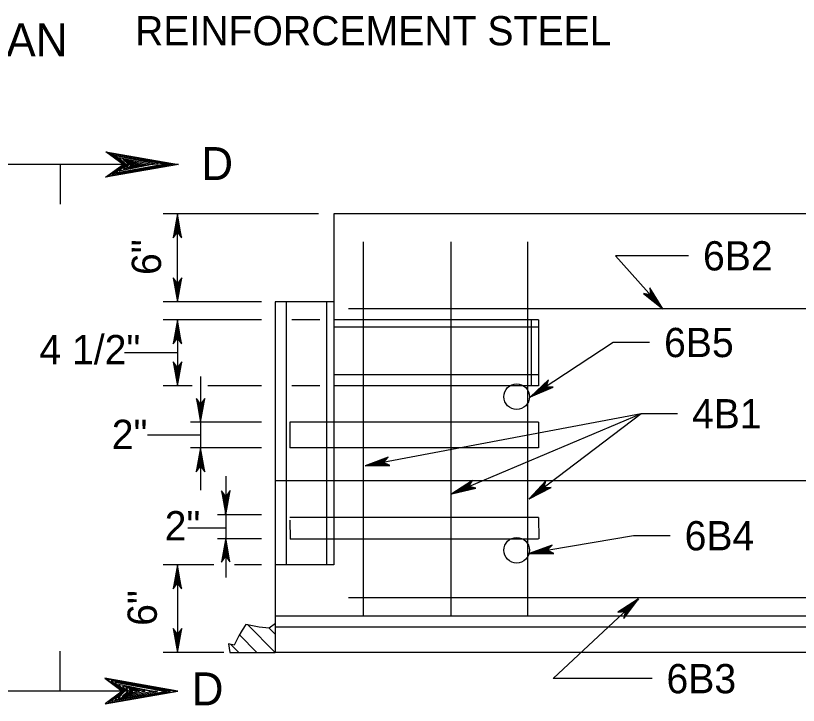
# Model space of a CAD drawing. Extents: x 499883 to 500983, y 499104 to 499764.
# Drawn here: x 500121.3 to 500228.2, y 499574 to 499668.3 of the extents above; entities that cross this region are included whole.
import ezdxf

# ---------------------------------------------------------------- set-up
doc = ezdxf.new("R2010")
doc.units = 0
for name, color, linetype in [('2', 7, 'Continuous'), ('24', 7, 'Continuous'), ('5', 7, 'Continuous'), ('60', 7, 'Continuous')]:
    doc.layers.add(name, color=color, linetype=linetype)

msp = doc.modelspace()

# ---------------------------------------------------------------- linework, layer by layer
at = {"layer": '2'}
for p, q in [((500127.4, 499642.49), (500127.4, 499647.93)), ((500127.3, 499581.39), (500127.3, 499575.94))]:
    msp.add_line(p, q, dxfattribs=at)
at = {"layer": '24'}
for points in [[(500143.38, 499641.16), (500142.8, 499637.88), (500143.38, 499638.66), (500143.95, 499637.9), (500143.38, 499641.16), (500143.39, 499640.94), (500142.85, 499637.97), (500143.39, 499638.73), (500143.91, 499638.03), (500143.4, 499640.82), (500143.38, 499640.71), (500142.93, 499638.17), (500143.39, 499638.74), (500143.83, 499638.16), (500143.38, 499640.66), (500143.4, 499640.55), (500143, 499638.33), (500143.38, 499638.77), (500143.78, 499638.32), (500143.4, 499640.24), (500143.4, 499640.05), (500143.08, 499638.5), (500143.37, 499638.8), (500143.7, 499638.48), (500143.38, 499640.02), (500143.37, 499639.85), (500143.17, 499638.68), (500143.4, 499638.9), (500143.62, 499638.66), (500143.38, 499639.68), (500143.37, 499639.52), (500143.23, 499638.82), (500143.39, 499638.93), (500143.56, 499638.74), (500143.38, 499639.43), (500143.27, 499638.98), (500143.4, 499639.04), (500143.52, 499638.84), (500143.4, 499639.32), (500143.32, 499639.02), (500143.42, 499639.14), (500143.48, 499639), (500143.39, 499639.14), (500143.37, 499639.07)], [(500143.38, 499629.17), (500143.96, 499632.44), (500143.38, 499631.66), (500142.81, 499632.42), (500143.38, 499629.17), (500143.38, 499629.38), (500143.92, 499632.35), (500143.38, 499631.6), (500142.86, 499632.29), (500143.37, 499629.5), (500143.38, 499629.61), (500143.83, 499632.15), (500143.38, 499631.58), (500142.93, 499632.17), (500143.38, 499629.66), (500143.37, 499629.77), (500143.77, 499631.99), (500143.38, 499631.56), (500142.98, 499632), (500143.37, 499630.08), (500143.37, 499630.27), (500143.68, 499631.82), (500143.39, 499631.52), (500143.07, 499631.85), (500143.38, 499630.3), (500143.39, 499630.48), (500143.59, 499631.65), (500143.37, 499631.42), (500143.14, 499631.66), (500143.38, 499630.64), (500143.4, 499630.8), (500143.53, 499631.5), (500143.38, 499631.39), (500143.2, 499631.58), (500143.38, 499630.89), (500143.49, 499631.35), (500143.37, 499631.28), (500143.24, 499631.48), (500143.37, 499631), (500143.44, 499631.3), (500143.34, 499631.18), (500143.28, 499631.32), (500143.38, 499631.18), (500143.39, 499631.25)], [(500143.38, 499626.67), (500142.8, 499623.39), (500143.38, 499624.18), (500143.95, 499623.41), (500143.38, 499626.67), (500143.39, 499626.45), (500142.85, 499623.49), (500143.39, 499624.24), (500143.91, 499623.54), (500143.4, 499626.33), (500143.38, 499626.22), (500142.93, 499623.68), (500143.39, 499624.25), (500143.83, 499623.67), (500143.38, 499626.17), (500143.4, 499626.07), (500143, 499623.84), (500143.38, 499624.28), (500143.78, 499623.84), (500143.4, 499625.75), (500143.4, 499625.56), (500143.08, 499624.01), (500143.37, 499624.31), (500143.7, 499623.99), (500143.38, 499625.53), (500143.37, 499625.36), (500143.17, 499624.19), (500143.4, 499624.41), (500143.62, 499624.17), (500143.38, 499625.2), (500143.37, 499625.03), (500143.23, 499624.33), (500143.39, 499624.44), (500143.56, 499624.25), (500143.38, 499624.95), (500143.27, 499624.49), (500143.4, 499624.55), (500143.52, 499624.35), (500143.4, 499624.83), (500143.32, 499624.53), (500143.42, 499624.66), (500143.48, 499624.51), (500143.39, 499624.66), (500143.37, 499624.58)], [(500143.38, 499617.67), (500143.96, 499620.95), (500143.38, 499620.17), (500142.81, 499620.93), (500143.38, 499617.67), (500143.38, 499617.89), (500143.92, 499620.86), (500143.38, 499620.11), (500142.86, 499620.8), (500143.37, 499618.01), (500143.38, 499618.12), (500143.83, 499620.66), (500143.38, 499620.09), (500142.93, 499620.67), (500143.38, 499618.17), (500143.37, 499618.28), (500143.77, 499620.5), (500143.38, 499620.07), (500142.98, 499620.51), (500143.37, 499618.59), (500143.37, 499618.78), (500143.68, 499620.33), (500143.39, 499620.03), (500143.07, 499620.36), (500143.38, 499618.81), (500143.39, 499618.99), (500143.59, 499620.15), (500143.37, 499619.93), (500143.14, 499620.17), (500143.38, 499619.15), (500143.4, 499619.31), (500143.53, 499620.01), (500143.38, 499619.9), (500143.2, 499620.09), (500143.38, 499619.4), (500143.49, 499619.85), (500143.37, 499619.79), (500143.24, 499619.99), (500143.37, 499619.51), (500143.44, 499619.81), (500143.34, 499619.69), (500143.28, 499619.83), (500143.38, 499619.69), (500143.39, 499619.76)], [(500146.53, 499612.68), (500147.11, 499615.95), (500146.53, 499615.17), (500145.96, 499615.94), (500146.53, 499612.68), (500146.52, 499612.9), (500147.06, 499615.86), (500146.52, 499615.11), (500146, 499615.8), (500146.51, 499613.01), (500146.53, 499613.12), (500146.98, 499615.66), (500146.52, 499615.09), (500146.08, 499615.68), (500146.53, 499613.17), (500146.51, 499613.28), (500146.91, 499615.5), (500146.53, 499615.07), (500146.13, 499615.51), (500146.51, 499613.6), (500146.51, 499613.78), (500146.83, 499615.34), (500146.54, 499615.03), (500146.21, 499615.36), (500146.53, 499613.81), (500146.54, 499613.99), (500146.74, 499615.16), (500146.51, 499614.93), (500146.29, 499615.18), (500146.53, 499614.15), (500146.55, 499614.31), (500146.68, 499615.02), (500146.52, 499614.9), (500146.35, 499615.09), (500146.53, 499614.4), (500146.64, 499614.86), (500146.51, 499614.79), (500146.39, 499614.99), (500146.51, 499614.52), (500146.59, 499614.82), (500146.49, 499614.69), (500146.43, 499614.83), (500146.52, 499614.69), (500146.54, 499614.77)], [(500146.53, 499609.18), (500145.95, 499605.91), (500146.53, 499606.69), (500147.1, 499605.92), (500146.53, 499609.18), (500146.53, 499608.96), (500145.99, 499606), (500146.54, 499606.75), (500147.05, 499606.06), (500146.54, 499608.85), (500146.53, 499608.74), (500146.08, 499606.2), (500146.54, 499606.77), (500146.98, 499606.18), (500146.53, 499608.69), (500146.54, 499608.58), (500146.14, 499606.36), (500146.53, 499606.79), (500146.93, 499606.35), (500146.55, 499608.26), (500146.54, 499608.08), (500146.23, 499606.52), (500146.52, 499606.83), (500146.84, 499606.5), (500146.53, 499608.04), (500146.52, 499607.87), (500146.32, 499606.7), (500146.55, 499606.93), (500146.77, 499606.68), (500146.53, 499607.71), (500146.51, 499607.54), (500146.38, 499606.84), (500146.54, 499606.96), (500146.71, 499606.77), (500146.53, 499607.46), (500146.42, 499607), (500146.54, 499607.07), (500146.67, 499606.87), (500146.55, 499607.34), (500146.47, 499607.04), (500146.57, 499607.17), (500146.63, 499607.02), (500146.54, 499607.17), (500146.52, 499607.09)], [(500143.38, 499593.19), (500142.8, 499589.92), (500143.38, 499590.7), (500143.95, 499589.94), (500143.38, 499593.19), (500143.39, 499592.98), (500142.85, 499590.01), (500143.39, 499590.76), (500143.91, 499590.07), (500143.4, 499592.86), (500143.38, 499592.75), (500142.93, 499590.21), (500143.39, 499590.78), (500143.83, 499590.19), (500143.38, 499592.7), (500143.4, 499592.59), (500143, 499590.37), (500143.38, 499590.8), (500143.78, 499590.36), (500143.4, 499592.27), (500143.4, 499592.09), (500143.08, 499590.54), (500143.37, 499590.84), (500143.7, 499590.51), (500143.38, 499592.06), (500143.37, 499591.88), (500143.17, 499590.71), (500143.4, 499590.94), (500143.62, 499590.69), (500143.38, 499591.72), (500143.37, 499591.56), (500143.23, 499590.85), (500143.39, 499590.97), (500143.56, 499590.78), (500143.38, 499591.47), (500143.27, 499591.01), (500143.4, 499591.08), (500143.52, 499590.88), (500143.4, 499591.36), (500143.32, 499591.06), (500143.42, 499591.18), (500143.48, 499591.04), (500143.39, 499591.18), (500143.37, 499591.11)], [(500206.38, 499588.55), (500203.55, 499586.71), (500204.53, 499586.82), (500204.36, 499585.87), (500206.38, 499588.55), (500206.22, 499588.39), (500203.65, 499586.74), (500204.58, 499586.86), (500204.42, 499585.99), (500206.14, 499588.3), (500206.05, 499588.24), (500203.85, 499586.81), (500204.59, 499586.87), (500204.47, 499586.13), (500206.01, 499588.2), (500205.94, 499588.12), (500204.02, 499586.88), (500204.61, 499586.89), (500204.55, 499586.29), (500205.71, 499587.9), (500205.57, 499587.77), (500204.2, 499586.93), (500204.63, 499586.92), (500204.61, 499586.45), (500205.54, 499587.76), (500205.4, 499587.65), (500204.39, 499586.98), (500204.72, 499586.97), (500204.69, 499586.64), (500205.29, 499587.53), (500205.15, 499587.42), (500204.54, 499587.04), (500204.73, 499587), (500204.71, 499586.74), (500205.1, 499587.35), (500204.69, 499587.12), (500204.82, 499587.07), (500204.76, 499586.84), (500205.03, 499587.26), (500204.75, 499587.11), (500204.91, 499587.12), (500204.85, 499586.98), (500204.89, 499587.15), (500204.82, 499587.11)], [(500143.38, 499581.22), (500143.96, 499584.5), (500143.38, 499583.71), (500142.81, 499584.48), (500143.38, 499581.22), (500143.38, 499581.44), (500143.92, 499584.4), (500143.38, 499583.65), (500142.86, 499584.35), (500143.37, 499581.56), (500143.38, 499581.67), (500143.83, 499584.2), (500143.38, 499583.64), (500142.93, 499584.22), (500143.38, 499581.72), (500143.37, 499581.82), (500143.77, 499584.04), (500143.38, 499583.61), (500142.98, 499584.05), (500143.37, 499582.14), (500143.37, 499582.32), (500143.68, 499583.88), (500143.39, 499583.58), (500143.07, 499583.9), (500143.38, 499582.36), (500143.39, 499582.53), (500143.59, 499583.7), (500143.37, 499583.48), (500143.14, 499583.72), (500143.38, 499582.69), (500143.4, 499582.86), (500143.53, 499583.56), (500143.38, 499583.44), (500143.2, 499583.64), (500143.38, 499582.94), (500143.49, 499583.4), (500143.37, 499583.34), (500143.24, 499583.54), (500143.37, 499583.06), (500143.44, 499583.36), (500143.34, 499583.23), (500143.28, 499583.38), (500143.38, 499583.23), (500143.39, 499583.31)]]:
    msp.add_lwpolyline(points, dxfattribs=at)
at = {"layer": '5'}
for p, q in [((500127.4, 499647.93), (500117.41, 499647.93)), ((500137.4, 499647.93), (500127.4, 499647.93)), ((500162.66, 499641.16), (500141.43, 499641.16)), ((500143.38, 499629.17), (500143.38, 499641.16)), ((500237.96, 499641.16), (500164.74, 499641.16)), ((500164.74, 499641.16), (500164.74, 499629.17)), ((500168.73, 499637.37), (500168.73, 499586.2)), ((500180.72, 499637.37), (500180.72, 499586.2)), ((500191.22, 499637.37), (500191.22, 499586.2)), ((500213.21, 499635.44), (500203.22, 499635.44)), ((500203.22, 499635.44), (500209.69, 499628.21)), ((500154.87, 499629.17), (500141.43, 499629.17)), ((500156.74, 499629.17), (500156.74, 499581.2)), ((500164.74, 499629.17), (500156.74, 499629.17)), ((500158.24, 499629.17), (500158.24, 499593.19)), ((500163.74, 499629.17), (500163.74, 499593.19)), ((500164.74, 499629.17), (500164.74, 499593.19)), ((500237.96, 499628.17), (500166.73, 499628.17)), ((500154.87, 499626.67), (500141.43, 499626.67)), ((500143.38, 499626.67), (500143.38, 499617.67)), ((500162.85, 499626.67), (500159, 499626.67)), ((500192.71, 499626.67), (500164.74, 499626.67)), ((500191.72, 499626.67), (500191.72, 499617.67)), ((500192.71, 499626.67), (500192.71, 499617.67)), ((500192.71, 499625.67), (500164.74, 499625.67)), ((500202.89, 499623.59), (500191.62, 499616.16)), ((500207.89, 499623.59), (500202.89, 499623.59)), ((500143.38, 499622.17), (500136.12, 499622.17)), ((500146.53, 499618.96), (500146.53, 499612.68)), ((500192.71, 499619.17), (500164.74, 499619.17)), ((500145.37, 499617.67), (500141.43, 499617.67)), ((500154.87, 499617.67), (500147.54, 499617.67)), ((500162.85, 499617.67), (500159, 499617.67)), ((500192.71, 499617.67), (500164.74, 499617.67)), ((500206.71, 499613.85), (500169.02, 499606.72)), ((500206.71, 499613.85), (500180.87, 499602.91)), ((500206.71, 499613.85), (500191.42, 499602.2)), ((500211.7, 499613.85), (500206.71, 499613.85)), ((500154.87, 499612.68), (500145.15, 499612.68)), ((500146.53, 499612.68), (500146.53, 499609.18)), ((500192.71, 499612.68), (500158.74, 499612.68)), ((500158.74, 499612.68), (500158.74, 499609.18)), ((500192.71, 499612.68), (500192.71, 499609.18)), ((500146.53, 499610.93), (500139.27, 499610.93)), ((500154.87, 499609.18), (500145.15, 499609.18)), ((500146.53, 499609.18), (500146.53, 499603.41)), ((500192.71, 499609.18), (500158.74, 499609.18)), ((500149.97, 499605.32), (500149.97, 499600.03)), ((500237.96, 499604.68), (500156.74, 499604.68)), ((500154.87, 499600.03), (500148.84, 499600.03)), ((500149.97, 499600.03), (500149.97, 499596.38)), ((500192.71, 499599.69), (500158.74, 499599.69)), ((500158.74, 499599.32), (500158.77, 499596.69)), ((500192.71, 499599.69), (500192.75, 499596.74)), ((500149.97, 499598.2), (500144.8, 499598.2)), ((500205.7, 499597.18), (500191.42, 499594.77)), ((500210.7, 499597.18), (500205.7, 499597.18)), ((500154.87, 499596.74), (500148.84, 499596.74)), ((500149.97, 499596.74), (500149.97, 499591.47)), ((500192.71, 499596.69), (500158.77, 499596.69)), ((500148.36, 499593.19), (500141.43, 499593.19)), ((500143.38, 499593.19), (500143.38, 499581.22)), ((500154.87, 499593.19), (500151.17, 499593.19)), ((500164.74, 499593.19), (500156.74, 499593.19)), ((500237.96, 499588.7), (500166.73, 499588.7)), ((500194.69, 499577.64), (500206.38, 499588.55)), ((500237.96, 499586.2), (500156.74, 499586.2)), ((500156.74, 499586.2), (500156.74, 499586.2)), ((500152.93, 499585.02), (500156.74, 499581.2)), ((500155.9, 499584.54), (500156.74, 499583.7)), ((500237.96, 499584.7), (500156.74, 499584.7)), ((500151.84, 499583.61), (500154.24, 499581.2)), ((500150.61, 499582.34), (500151.75, 499581.2)), ((500149.69, 499581.21), (500141.43, 499581.21)), ((500237.96, 499581.2), (500156.74, 499581.2)), ((500208.22, 499577.64), (500194.69, 499577.64)), ((500127.3, 499575.94), (500117.31, 499575.94)), ((500137.3, 499575.94), (500127.3, 499575.94))]:
    msp.add_line(p, q, dxfattribs=at)
for points in [[(500143.53, 499647.93), (500133.56, 499646.17), (500135.94, 499647.93), (500133.61, 499649.67), (500143.53, 499647.93), (500142.87, 499647.95), (500133.84, 499646.3), (500136.13, 499647.95), (500134.01, 499649.53), (500142.51, 499647.98), (500142.18, 499647.93), (500134.44, 499646.56), (500136.18, 499647.95), (500134.39, 499649.31), (500142.03, 499647.93), (500141.69, 499647.98), (500134.93, 499646.76), (500136.25, 499647.93), (500134.91, 499649.15), (500140.73, 499647.98), (500140.17, 499647.98), (500135.43, 499647.01), (500136.36, 499647.91), (500135.36, 499648.9), (500140.07, 499647.93), (500139.54, 499647.9), (500135.98, 499647.29), (500136.66, 499647.98), (500135.92, 499648.67), (500139.05, 499647.93), (500138.54, 499647.88), (500136.41, 499647.47), (500136.76, 499647.95), (500136.18, 499648.49), (500138.28, 499647.93), (500136.89, 499647.6), (500137.09, 499647.98), (500136.48, 499648.36), (500137.93, 499647.98), (500137.02, 499647.75), (500137.4, 499648.06), (500136.96, 499648.24), (500137.4, 499647.95), (500137.17, 499647.91)], [(500209.69, 499628.21), (500207.91, 499631.08), (500208.01, 499630.1), (500207.06, 499630.29), (500209.69, 499628.21), (500209.54, 499628.37), (500207.94, 499630.98), (500208.04, 499630.05), (500207.18, 499630.22), (500209.46, 499628.46), (500209.39, 499628.55), (500208.01, 499630.78), (500208.05, 499630.03), (500207.32, 499630.18), (500209.36, 499628.59), (500209.27, 499628.66), (500208.07, 499630.61), (500208.07, 499630.02), (500207.47, 499630.08), (500209.06, 499628.9), (500208.93, 499629.04), (500208.12, 499630.43), (500208.11, 499630), (500207.64, 499630.03), (500208.92, 499629.07), (500208.81, 499629.21), (500208.17, 499630.23), (500208.15, 499629.91), (500207.82, 499629.94), (500208.7, 499629.33), (500208.6, 499629.46), (500208.22, 499630.08), (500208.18, 499629.89), (500207.92, 499629.92), (500208.53, 499629.52), (500208.3, 499629.94), (500208.25, 499629.8), (500208.02, 499629.87), (500208.44, 499629.59), (500208.29, 499629.87), (500208.3, 499629.71), (500208.16, 499629.78), (500208.33, 499629.73), (500208.29, 499629.8)], [(500191.62, 499616.16), (500194.72, 499617.5), (500193.73, 499617.55), (500194.06, 499618.47), (500191.62, 499616.16), (500191.8, 499616.29), (500194.61, 499617.49), (500193.67, 499617.53), (500193.97, 499618.35), (500191.89, 499616.36), (500191.99, 499616.41), (500194.4, 499617.45), (500193.66, 499617.52), (500193.91, 499618.22), (500192.04, 499616.44), (500192.12, 499616.51), (500194.23, 499617.41), (500193.64, 499617.5), (500193.79, 499618.08), (500192.39, 499616.69), (500192.54, 499616.79), (500194.04, 499617.39), (500193.62, 499617.47), (500193.71, 499617.93), (500192.58, 499616.8), (500192.73, 499616.89), (500193.84, 499617.37), (500193.52, 499617.44), (500193.6, 499617.76), (500192.87, 499616.98), (500193.01, 499617.06), (500193.68, 499617.34), (500193.5, 499617.41), (500193.56, 499617.67), (500193.08, 499617.12), (500193.53, 499617.29), (500193.4, 499617.36), (500193.5, 499617.58), (500193.17, 499617.2), (500193.46, 499617.31), (500193.3, 499617.32), (500193.39, 499617.45), (500193.32, 499617.29), (500193.39, 499617.32)], [(500169.02, 499606.72), (500172.4, 499606.76), (500171.51, 499607.19), (500172.16, 499607.91), (500169.02, 499606.72), (500169.24, 499606.77), (500172.3, 499606.79), (500171.45, 499607.19), (500172.04, 499607.84), (500169.35, 499606.8), (500169.46, 499606.81), (500172.08, 499606.84), (500171.43, 499607.18), (500171.93, 499607.74), (500169.51, 499606.82), (500169.62, 499606.85), (500171.91, 499606.87), (500171.41, 499607.17), (500171.77, 499607.66), (500169.94, 499606.91), (500170.12, 499606.95), (500171.73, 499606.92), (500171.37, 499607.16), (500171.64, 499607.54), (500170.16, 499606.94), (500170.33, 499606.96), (500171.54, 499606.98), (500171.27, 499607.16), (500171.47, 499607.43), (500170.49, 499607), (500170.66, 499607.02), (500171.38, 499607.01), (500171.24, 499607.15), (500171.4, 499607.36), (500170.74, 499607.05), (500171.22, 499607.03), (500171.13, 499607.14), (500171.3, 499607.3), (500170.85, 499607.09), (500171.17, 499607.07), (500171.02, 499607.14), (500171.15, 499607.23), (500171.03, 499607.11), (500171.11, 499607.11)], [(500180.87, 499602.91), (500184.16, 499603.66), (500183.2, 499603.89), (500183.69, 499604.73), (500180.87, 499602.91), (500181.07, 499603), (500184.06, 499603.67), (500183.14, 499603.88), (500183.59, 499604.63), (500181.18, 499603.05), (500181.29, 499603.08), (500183.84, 499603.67), (500183.13, 499603.87), (500183.5, 499604.52), (500181.33, 499603.1), (500181.43, 499603.16), (500183.66, 499603.67), (500183.11, 499603.85), (500183.36, 499604.4), (500181.72, 499603.29), (500181.9, 499603.36), (500183.48, 499603.68), (500183.08, 499603.83), (500183.25, 499604.26), (500181.93, 499603.36), (500182.1, 499603.42), (500183.27, 499603.69), (500182.97, 499603.82), (500183.11, 499604.12), (500182.25, 499603.49), (500182.41, 499603.54), (500183.12, 499603.69), (500182.95, 499603.79), (500183.06, 499604.03), (500182.48, 499603.59), (500182.95, 499603.67), (500182.84, 499603.76), (500182.98, 499603.96), (500182.58, 499603.65), (500182.89, 499603.7), (500182.74, 499603.74), (500182.85, 499603.85), (500182.75, 499603.71), (500182.83, 499603.72)], [(500191.42, 499602.2), (500194.42, 499603.75), (500193.43, 499603.74), (500193.7, 499604.67), (500191.42, 499602.2), (500191.59, 499602.34), (500194.32, 499603.73), (500193.38, 499603.7), (500193.62, 499604.55), (500191.68, 499602.42), (500191.78, 499602.48), (500194.1, 499603.67), (500193.36, 499603.69), (500193.56, 499604.41), (500191.82, 499602.51), (500191.89, 499602.59), (500193.93, 499603.63), (500193.35, 499603.67), (500193.46, 499604.27), (500192.15, 499602.78), (500192.3, 499602.9), (500193.75, 499603.59), (500193.32, 499603.65), (500193.39, 499604.11), (500192.33, 499602.9), (500192.48, 499603), (500193.55, 499603.56), (500193.23, 499603.6), (500193.29, 499603.94), (500192.61, 499603.11), (500192.75, 499603.2), (500193.4, 499603.52), (500193.21, 499603.58), (500193.25, 499603.84), (500192.81, 499603.26), (500193.24, 499603.46), (500193.11, 499603.52), (500193.2, 499603.74), (500192.89, 499603.35), (500193.18, 499603.47), (500193.02, 499603.47), (500193.1, 499603.61), (500193.04, 499603.45), (500193.11, 499603.48)], [(500149.97, 499600.03), (500150.56, 499603.35), (500149.97, 499602.56), (500149.39, 499603.33), (500149.97, 499600.03), (500149.96, 499600.25), (500150.51, 499603.26), (500149.96, 499602.49), (500149.44, 499603.2), (500149.95, 499600.37), (500149.97, 499600.48), (500150.43, 499603.05), (500149.96, 499602.48), (500149.51, 499603.07), (500149.97, 499600.53), (500149.95, 499600.64), (500150.36, 499602.89), (500149.97, 499602.45), (500149.56, 499602.9), (500149.95, 499600.96), (500149.95, 499601.15), (500150.27, 499602.72), (500149.98, 499602.42), (500149.65, 499602.75), (500149.97, 499601.18), (500149.98, 499601.36), (500150.18, 499602.54), (500149.95, 499602.32), (500149.72, 499602.56), (500149.97, 499601.52), (500149.98, 499601.69), (500150.12, 499602.4), (500149.96, 499602.28), (500149.78, 499602.48), (500149.97, 499601.77), (500150.08, 499602.24), (500149.95, 499602.17), (500149.82, 499602.38), (500149.95, 499601.89), (500150.03, 499602.2), (500149.93, 499602.07), (500149.87, 499602.21), (500149.96, 499602.07), (500149.98, 499602.15)], [(500149.97, 499596.9), (500149.38, 499593.57), (500149.97, 499594.37), (500150.55, 499593.59), (500149.97, 499596.9), (500149.97, 499596.68), (500149.42, 499593.67), (500149.98, 499594.43), (500150.5, 499593.72), (500149.98, 499596.56), (500149.97, 499596.45), (500149.51, 499593.87), (500149.97, 499594.45), (500150.43, 499593.85), (500149.97, 499596.4), (500149.98, 499596.29), (500149.58, 499594.03), (500149.97, 499594.47), (500150.37, 499594.02), (500149.98, 499595.96), (500149.98, 499595.78), (500149.66, 499594.2), (500149.96, 499594.51), (500150.29, 499594.18), (500149.97, 499595.74), (500149.96, 499595.57), (500149.75, 499594.38), (500149.98, 499594.61), (500150.21, 499594.36), (500149.97, 499595.4), (500149.95, 499595.24), (500149.81, 499594.52), (500149.98, 499594.64), (500150.15, 499594.45), (500149.97, 499595.15), (500149.86, 499594.68), (500149.98, 499594.75), (500150.11, 499594.55), (500149.98, 499595.03), (500149.91, 499594.73), (500150.01, 499594.85), (500150.07, 499594.71), (500149.98, 499594.85), (500149.96, 499594.78)], [(500191.42, 499594.77), (500194.79, 499594.75), (500193.91, 499595.19), (500194.58, 499595.89), (500191.42, 499594.77), (500191.63, 499594.82), (500194.69, 499594.77), (500193.85, 499595.19), (500194.46, 499595.83), (500191.75, 499594.84), (500191.86, 499594.85), (500194.48, 499594.82), (500193.83, 499595.19), (500194.34, 499595.73), (500191.91, 499594.86), (500192.02, 499594.89), (500194.31, 499594.86), (500193.81, 499595.18), (500194.18, 499595.65), (500192.33, 499594.94), (500192.52, 499594.97), (500194.13, 499594.92), (500193.78, 499595.16), (500194.05, 499595.54), (500192.55, 499594.96), (500192.73, 499594.98), (500193.93, 499594.98), (500193.67, 499595.17), (500193.88, 499595.44), (500192.89, 499595.02), (500193.06, 499595.03), (500193.78, 499595.02), (500193.64, 499595.16), (500193.8, 499595.36), (500193.14, 499595.06), (500193.62, 499595.03), (500193.53, 499595.15), (500193.71, 499595.3), (500193.25, 499595.1), (500193.57, 499595.07), (500193.42, 499595.15), (500193.56, 499595.24), (500193.43, 499595.12), (500193.51, 499595.12)], [(500156.77, 499585.16), (500155.9, 499584.54), (500154.55, 499584.7), (500152.71, 499585.06), (500152.24, 499584.27), (500151.77, 499583.49), (500151.14, 499582.23), (500150.35, 499582.39), (500150.53, 499581.21), (500156.74, 499581.2)], [(500143.43, 499575.94), (500133.46, 499577.71), (500135.84, 499575.94), (500133.51, 499574.21), (500143.43, 499575.94), (500142.77, 499575.92), (500133.74, 499577.57), (500136.03, 499575.92), (500133.91, 499574.34), (500142.41, 499575.89), (500142.08, 499575.94), (500134.34, 499577.32), (500136.08, 499575.92), (500134.29, 499574.57), (500141.92, 499575.94), (500141.59, 499575.89), (500134.83, 499577.11), (500136.15, 499575.94), (500134.8, 499574.73), (500140.63, 499575.89), (500140.07, 499575.89), (500135.33, 499576.86), (500136.25, 499575.97), (500135.26, 499574.98), (500139.97, 499575.94), (500139.44, 499575.97), (500135.88, 499576.58), (500136.56, 499575.89), (500135.82, 499575.21), (500138.95, 499575.94), (500138.44, 499575.99), (500136.31, 499576.4), (500136.66, 499575.92), (500136.08, 499575.39), (500138.18, 499575.94), (500136.79, 499576.27), (500136.99, 499575.89), (500136.38, 499575.51), (500137.83, 499575.89), (500136.92, 499576.12), (500137.3, 499575.82), (500136.86, 499575.64), (500137.3, 499575.92), (500137.07, 499575.97)]]:
    msp.add_lwpolyline(points, dxfattribs=at)
at = {"layer": '60'}
for centre in [(500189.72, 499616.18), (500189.72, 499595.19)]:
    msp.add_circle(centre, 1.75, dxfattribs=at)

# ---------------------------------------------------------------- texts
at = {"layer": '5'}
for s, height, p in [('REINFORCEMENT STEEL', 4, (500137.58, 499664.21)), ('PLAN', 4.5, (500112.64, 499662.71)), ('D', 4.5, (500146.63, 499645.8)), ('6B2', 4, (500215.18, 499633.44)), ('4 1/2"', 4, (500124.51, 499620.62)), ('6B5', 4, (500209.86, 499621.59)), ('4B1', 4, (500213.67, 499611.85)), ('2"', 4, (500134.4, 499609.03)), ('2"', 4, (500141.63, 499596.54)), ('6B4', 4, (500212.67, 499595.18)), ('6B3', 4, (500210.19, 499575.64)), ('D', 4.5, (500145.32, 499573.99))]:
    msp.add_text(s, height=height, dxfattribs=at).set_placement(p)
for p in [(500141.13, 499632.82), (500140.56, 499584.86)]:
    msp.add_text('6"', height=4, rotation=90, dxfattribs=at).set_placement(p)

doc.saveas('drawing.dxf')
